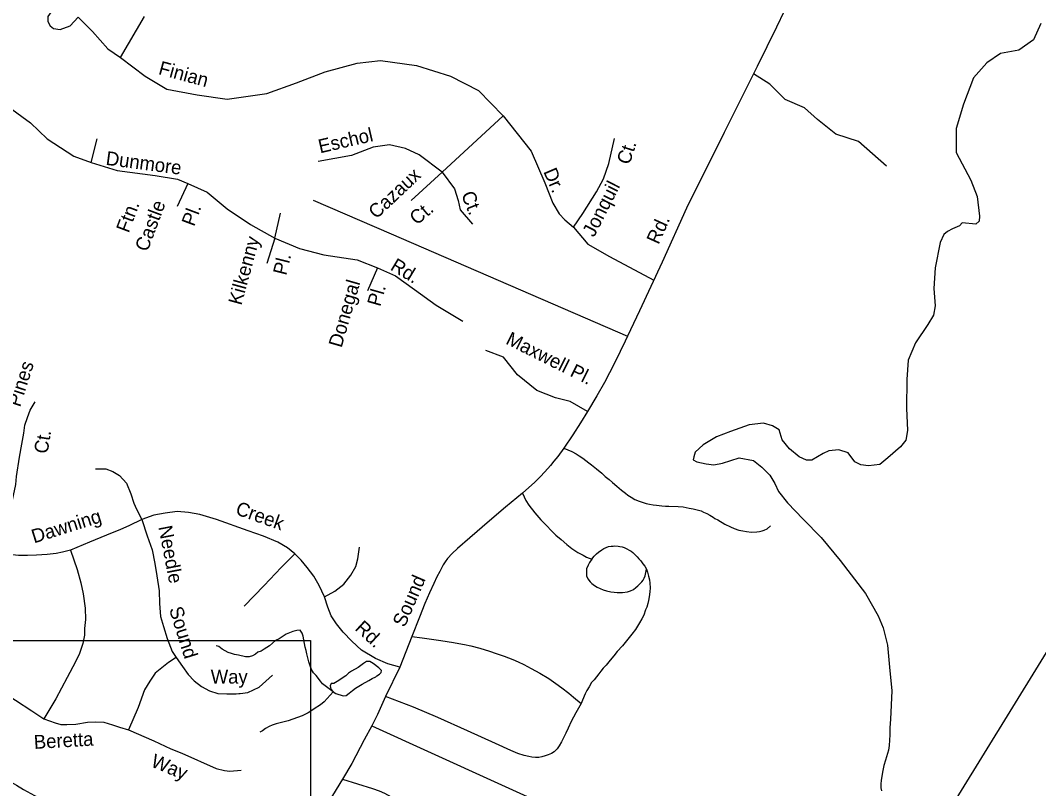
# Model space of a CAD drawing. Extents: x 1945482 to 2853149, y 66427 to 1015778.
# Drawn here: x 2344687 to 2349522, y 153897 to 157546 of the extents above; entities that cross this region are included whole.
import ezdxf

# ---------------------------------------------------------------- set-up
doc = ezdxf.new("R2010")
doc.units = 0
for name, color, linetype in [('Old_Level_10', 7, 'Continuous'), ('Old_Level_35', 7, 'Continuous'), ('Old_Level_48', 7, 'Continuous'), ('Old_Level_49', 7, 'Continuous'), ('Old_Level_59', 7, 'Continuous'), ('Old_Level_60', 7, 'Continuous'), ('Old_Level_63', 7, 'Continuous')]:
    doc.layers.add(name, color=color, linetype=linetype)

msp = doc.modelspace()

# ---------------------------------------------------------------- linework, layer by layer
at = {"layer": 'Old_Level_35'}
for p, q in [((2346077, 156693.2), (2346447.3, 156532.6)), ((2346447.3, 156532.6), (2347570.1, 156045.9))]:
    msp.add_line(p, q, dxfattribs=at)
for points in [[(2344345.4, 157787.9), (2344516.4, 157777.7), (2344670.4, 157757.1), (2344790.2, 157722.9), (2344892.8, 157651), (2344848.3, 157609.9), (2344817.5, 157565.4), (2344817.5, 157541.4), (2344827.8, 157520.9), (2344844.9, 157507.2), (2344875.7, 157503.8), (2344923.6, 157520.9), (2344961.3, 157562), (2345029.7, 157493.5), (2345101.5, 157411.3), (2345163.1, 157370.2), (2345276.1, 157565.4)], [(2348350.3, 157668.4), (2348276.4, 157513.5), (2348185.6, 157327.7), (2348028, 157013.6), (2347850.2, 156654.4), (2347734.3, 156397.8), (2347627.3, 156167.4), (2347570.1, 156045.9), (2347559.2, 156022.6), (2347510.9, 155924.5), (2347485, 155871.6), (2347460.9, 155826.7), (2347423.4, 155763.2), (2347380.3, 155689.3), (2347346.4, 155634.1), (2347310.5, 155578.5), (2347267.1, 155514.8), (2347238.5, 155475.6), (2347219.4, 155452.8), (2347204.4, 155432.2), (2347177.4, 155401.3), (2347154.4, 155378.4), (2347129.4, 155353.4), (2347071.4, 155300.9), (2346990.1, 155233.7), (2346914.5, 155168.7), (2346821.8, 155089.2), (2346761.8, 155038.6), (2346736.5, 155013.6), (2346715.5, 154990.8), (2346704.3, 154974.3), (2346694.7, 154960.1), (2346678.2, 154929.3), (2346665.1, 154902.8), (2346650.2, 154872), (2346630, 154827.2), (2346608.1, 154776.5), (2346582.7, 154711.5), (2346546.3, 154620.1), (2346488.1, 154473.7)], [(2345163.1, 157370.2), (2345279.5, 157281.2), (2345382.1, 157219.6), (2345525.8, 157192.2), (2345669.5, 157171.6), (2345857.7, 157199), (2345998, 157250.4), (2346134.9, 157301.7), (2346285.4, 157342.8), (2346397, 157356.5), (2346568.1, 157332.5), (2346728.9, 157281.2), (2346862.3, 157212.7), (2346978.7, 157092.9), (2347112.1, 156925.1), (2347177.1, 156774.4), (2347214.8, 156678.6), (2347245.6, 156627.2), (2347272.9, 156599.8), (2347312.6, 156564.9), (2347357.1, 156629.9), (2347422.1, 156732.7), (2347456.3, 156794.3), (2347480.3, 156866.2), (2347507.7, 156986)], [(2348246, 157242.9), (2348167.6, 157291.9)], [(2348798.9, 156853.2), (2348666.8, 156971.5), (2348559, 157006.3), (2348472.1, 157075.9), (2348409.5, 157131.5), (2348319.1, 157169.8), (2348246, 157242.9)], [(2344629.4, 157138.1), (2344735.4, 157059.3), (2344814.1, 156984), (2344940.7, 156901.8), (2345022.8, 156871), (2345146, 156833.3), (2345327.4, 156809.4), (2345433.4, 156792.2), (2345481.4, 156771.7), (2345573.7, 156730.6), (2345669.5, 156651.8), (2345779, 156576.5), (2345895.4, 156511.5), (2346011.7, 156463.5), (2346128.1, 156432.7), (2346285.4, 156408.7), (2346383.3, 156371.1), (2346468.8, 156333.4), (2346557.8, 156268.4), (2346660.5, 156193), (2346787.1, 156117.7)], [(2346978.7, 157092.9), (2346689.9, 156825.1), (2346542.8, 156691.6)], [(2345022.8, 156871), (2345052.3, 156984)], [(2346689.9, 156825.1), (2346580.4, 156907.3), (2346515.4, 156938.1), (2346440.1, 156955.2), (2346361.4, 156944.9), (2346258.8, 156903.9), (2346101.4, 156876.5)], [(2346689.9, 156825.1), (2346748.1, 156746.4), (2346765.2, 156691.6), (2346775.4, 156647.1), (2346833.6, 156578.6)], [(2345481.4, 156771.7), (2345432.1, 156662.1)], [(2345895.4, 156511.5), (2345921.4, 156631.3)], [(2347312.6, 156564.9), (2347381.1, 156482.7), (2347483.7, 156424.5)], [(2345895.4, 156511.5), (2345856.4, 156391.6)], [(2347483.7, 156424.5), (2347695, 156313.2)], [(2346383.3, 156371.1), (2346335.4, 156261.5)], [(2347380.3, 155689.3), (2347297.6, 155735.7), (2347227.2, 155753.4), (2347139.1, 155788.6), (2347046.7, 155863.5), (2346980.7, 155947.2), (2346897, 155978)], [(2344564.8, 155028.4), (2344575.6, 155055.3), (2344597.1, 155102), (2344618.6, 155148.6), (2344634.7, 155202.4), (2344645.5, 155247.2), (2344654.4, 155290.3), (2344665.2, 155342.3), (2344668.8, 155379.9), (2344683.1, 155471.4), (2344693.9, 155534.2), (2344702.8, 155586.2), (2344708.2, 155623.9), (2344720.7, 155659.7), (2344733.3, 155695.6), (2344756.6, 155735)], [(2347267.1, 155514.8), (2347305.8, 155498.3), (2347326.3, 155487.3), (2347340.5, 155477.6), (2347357, 155466.5), (2347385.7, 155445.6), (2347398.2, 155435.9), (2347423, 155416.9), (2347447.7, 155395.9), (2347464.4, 155380.5), (2347483.1, 155365.5), (2347497.7, 155351.9), (2347518.4, 155334.7), (2347541.2, 155315.6), (2347559.8, 155300.2), (2347572, 155290.9), (2347586.5, 155281.3), (2347605, 155270.2), (2347625.3, 155262.8), (2347639.3, 155257.4), (2347657.6, 155252.2), (2347673.8, 155248.9), (2347692, 155245.4), (2347708.1, 155244.1), (2347732.2, 155241.1), (2347750.3, 155239.8), (2347766.1, 155238.5), (2347810.1, 155238.2), (2347834.5, 155235.3), (2347862.6, 155230.1), (2347880.8, 155226.9), (2347894.7, 155223.5), (2347919.3, 155216.6), (2347931.3, 155210.9), (2347945.7, 155203.6), (2347960.1, 155196.3), (2347976.2, 155186.7), (2347984.7, 155181.1), (2347998.8, 155173.5), (2348031.7, 155152.8), (2348058.2, 155140.1), (2348076.5, 155132.6), (2348098.8, 155125.6), (2348117, 155122.4), (2348135.1, 155119.2), (2348159.2, 155115.9), (2348183.2, 155116.8), (2348197.2, 155119.3), (2348208.9, 155122.1), (2348219, 155124.4), (2348232.5, 155130.9), (2348248, 155145.6)], [(2345043.3, 155415.8), (2345093.5, 155415.8), (2345125.7, 155403.3), (2345158, 155385.3), (2345190.2, 155347.7), (2345211.8, 155297.4), (2345226.1, 155252.6), (2345238.7, 155224.8), (2345263.7, 155175.5)], [(2347071.4, 155300.9), (2347086.9, 155265.8), (2347101.6, 155244), (2347129.3, 155207.4), (2347158.5, 155174.4), (2347183.4, 155149.5), (2347210.5, 155120.3), (2347229.3, 155101.1), (2347254.1, 155080), (2347281.3, 155057.2), (2347306, 155038.1), (2347334.6, 155019.2), (2347359.1, 155006.4), (2347375.6, 154996.9), (2347399.9, 154988)], [(2345989.5, 155012.3), (2345955.4, 155041), (2345908.8, 155067.9), (2345840.8, 155096.6), (2345769.1, 155121.7), (2345618.5, 155175.5), (2345539.7, 155198.8), (2345485.9, 155209.6), (2345432.2, 155213.2), (2345374.8, 155206), (2345321.1, 155197), (2345263.7, 155175.5)], [(2345263.7, 155175.5), (2345201.6, 155145.2), (2345161.6, 155128.9), (2345095.3, 155102), (2345014.6, 155067.9), (2344925, 155030.2)], [(2345263.7, 155175.5), (2345289.7, 155097.5), (2345313, 155031.1), (2345325.5, 154966.6), (2345334.5, 154907.4), (2345345.3, 154837.4), (2345347, 154776.4), (2345352.4, 154715.5), (2345366.8, 154667), (2345384.7, 154609.7), (2345408, 154548.7), (2345426.8, 154520.9)], [(2344925, 155030.2), (2344887.4, 155021.3), (2344856.9, 155014.1), (2344813.9, 155008.7), (2344763.7, 155006.9), (2344720.7, 155005.1), (2344677.7, 155005.1), (2344634.7, 155008.7), (2344602.5, 155014.1), (2344564.8, 155028.4)], [(2344925, 155030.2), (2344956.4, 154937.9), (2344974.3, 154875.1), (2344985.1, 154823.1), (2344994, 154754.9), (2344995.8, 154701.1), (2344992.2, 154658.1), (2344992.2, 154625.8), (2344983.3, 154586.3), (2344967.1, 154539.7), (2344949.2, 154500.3), (2344909.8, 154424.9), (2344856, 154324.5), (2344798.7, 154229.4)], [(2345989.5, 155012.3), (2345925, 154947.7), (2345844.3, 154861.6), (2345749.4, 154764.8)], [(2346131.1, 154807.8), (2346106, 154861.6), (2346080.9, 154906.5), (2346048.6, 154947.7), (2346020, 154981.8), (2345989.5, 155012.3)], [(2346131.1, 154807.8), (2346179.4, 154834.7), (2346222.5, 154868.8), (2346256.5, 154911.9), (2346279.8, 154953.1), (2346288.8, 154989), (2346297.7, 155044.6)], [(2347399.9, 154988), (2347411.5, 155002.2), (2347422.9, 155012.9), (2347432.7, 155021.1), (2347448.4, 155031.9), (2347458, 155038.2), (2347468, 155042.6), (2347479.6, 155047), (2347491.7, 155049.4), (2347501.5, 155049.8), (2347509.7, 155050.1), (2347525.5, 155048.8), (2347533.8, 155047.1), (2347543.7, 155045.5), (2347554, 155042), (2347566, 155036.6), (2347578.4, 155030.8), (2347586.5, 155025.3), (2347594.9, 155019.7), (2347603.1, 155011.8), (2347615.8, 154998.5), (2347624, 154988.7), (2347632.3, 154979.1), (2347643, 154965.5), (2347651.3, 154954), (2347660.1, 154940.2)], [(2347399.9, 154988), (2347388.7, 154971.5), (2347383, 154959.1), (2347375.8, 154940.8), (2347374.4, 154926.9), (2347375.1, 154908.9), (2347381.6, 154893.1), (2347392.4, 154879.4), (2347400.5, 154871.8), (2347413.1, 154862.5), (2347425.2, 154854.8), (2347439.6, 154847.5), (2347453.9, 154842.1), (2347469.9, 154836.5), (2347490.1, 154831.4), (2347506.2, 154830.1), (2347520.4, 154828.7), (2347532.2, 154829.1), (2347546.3, 154829.7), (2347570.1, 154832.6), (2347584.1, 154837.1), (2347597.6, 154843.5), (2347609.4, 154852.2), (2347619.3, 154860.5), (2347630.6, 154871.1), (2347638.2, 154879.3), (2347644.1, 154887.4), (2347649.6, 154897.8), (2347653.2, 154907.8), (2347660.1, 154940.2)], [(2347660.1, 154940.2), (2347664.6, 154926.3), (2347669.3, 154906.4), (2347673.9, 154888.6), (2347676.5, 154872.9), (2347677.4, 154851), (2347676.1, 154832.9), (2347673.2, 154808.5), (2347669.9, 154790.6), (2347666.6, 154776.4), (2347661, 154760), (2347655.6, 154746.1), (2347646.7, 154721.4), (2347637.3, 154703.3), (2347626.2, 154684.8), (2347616.7, 154668.4), (2347607.4, 154653.9), (2347590.2, 154631.2), (2347571.2, 154606.5), (2347546.5, 154575.7), (2347521.3, 154548.4), (2347504.1, 154527.7), (2347487.2, 154507), (2347468.1, 154484.3), (2347454.5, 154469.9), (2347442.9, 154455.4), (2347433.6, 154442.9), (2347410.8, 154414.1), (2347399.1, 154401.5), (2347388.1, 154381.3), (2347376.7, 154362.8), (2347369.4, 154348.4), (2347356.5, 154318), (2347349.2, 154301.7)], [(2346488.1, 154473.7), (2346432.1, 154490.4), (2346373, 154515.5), (2346306.7, 154555), (2346260.1, 154598), (2346218.9, 154641), (2346188.4, 154680.5), (2346163.3, 154718.2), (2346147.2, 154759.4), (2346131.1, 154807.8)], [(2346546.3, 154620.1), (2346594.5, 154613.8), (2346638.7, 154607.7), (2346660.8, 154604.6), (2346682.9, 154601.2), (2346713.3, 154596.5), (2346743.4, 154591.8), (2346769.5, 154586.9), (2346796, 154581.7), (2346826.1, 154575.1), (2346868.5, 154564.6), (2346915, 154550.7), (2346945.6, 154539.7), (2346983.9, 154527.1), (2347024.6, 154510.7), (2347051.3, 154499.9), (2347077.7, 154486.9), (2347112.3, 154468.2), (2347153.2, 154445.9), (2347196.2, 154419.7), (2347229.3, 154397), (2347258, 154376.2), (2347291.2, 154351.2), (2347313.9, 154332.1), (2347349.2, 154301.7)], [(2345426.8, 154520.9), (2345391, 154495.8), (2345358.7, 154470.7), (2345326.4, 154445.6), (2345301.4, 154407.9), (2345276.3, 154366.6), (2345245.8, 154282.4), (2345201, 154176.5)], [(2345426.8, 154520.9), (2345457.3, 154477.8), (2345484.1, 154440.2), (2345512.8, 154409.7), (2345546.9, 154382.8), (2345584.5, 154361.3), (2345623.9, 154348.7), (2345666.9, 154346.9), (2345711.7, 154346.9), (2345724.4, 154348.5), (2345730.1, 154349.3)], [(2345730.1, 154349.3), (2345767.3, 154354.1), (2345821, 154379.2), (2345883.8, 154436.6)], [(2346488.1, 154473.7), (2346421.4, 154334.9), (2346382.8, 154249.3), (2346355, 154196.4), (2346319.6, 154128.7), (2346260, 154016.4), (2346217, 153942.8), (2346134.1, 153807.2), (2346044.2, 153655.7), (2345936.8, 153483.4), (2345813.2, 153273.7)], [(2344492.3, 154424.9), (2344578.3, 154371.1), (2344664.3, 154317.3), (2344741.3, 154267.1), (2344798.7, 154229.4)], [(2347349.2, 154301.7), (2347324.8, 154256.7), (2347302.4, 154215.8), (2347287.6, 154185), (2347276.7, 154160.6), (2347265.5, 154138.2), (2347256.3, 154119.8), (2347244.9, 154101.3), (2347235.6, 154087.1), (2347222.1, 154072.5), (2347208.3, 154064.1), (2347192.8, 154057.2), (2347178.9, 154052.7), (2347163, 154048.1), (2347149, 154045.6), (2347133.3, 154045), (2347115.2, 154046.3), (2347100.9, 154049.6), (2347078.7, 154054.7), (2347048.5, 154063.6), (2347015.8, 154078.4), (2346942.6, 154111.3), (2346809.9, 154172.4), (2346669.5, 154234.7), (2346553.4, 154284), (2346421.4, 154334.9)], [(2344798.7, 154229.4), (2344851.6, 154210.6), (2344878.4, 154201.6), (2344907.1, 154201.6), (2344950.1, 154203.4), (2345005.7, 154212.4), (2345045.1, 154214.2), (2345082.7, 154212.4), (2345123.9, 154199.9), (2345158, 154189.1), (2345201, 154176.5)], [(2346355, 154196.4), (2347535.3, 153659.3)], [(2345201, 154176.5), (2345321.1, 154124.5), (2345401.7, 154086.9), (2345453.7, 154065.3), (2345616.7, 153993.6), (2345656.2, 153982.8), (2345681.3, 153981.1), (2345735, 153984.6)], [(2343938.9, 154016.8), (2344260.2, 153991.4), (2344452.9, 153975.1), (2344499, 153970.7), (2344529.3, 153967.9), (2344549.5, 153964.8), (2344559.4, 153963.2), (2344571.7, 153959.8), (2344583.6, 153956), (2344606, 153947), (2344634.8, 153932.1), (2344669.3, 153913.4), (2344702.3, 153892.7), (2344753.3, 153864.9), (2344929.2, 153765.8), (2345152.2, 153646.6), (2345479.6, 153459.4), (2345813.2, 153273.7)], [(2346217, 153942.8), (2346358.6, 153898.2), (2346391.2, 153887.6), (2346415.6, 153876.5), (2346448.1, 153857.7), (2346464.7, 153846.6), (2346485.3, 153831.3), (2346504, 153814), (2346522.8, 153796.7), (2346541.4, 153781.3), (2346555.7, 153770.1), (2346582.6, 153753.1), (2346598.7, 153743.6), (2346619.1, 153734.5), (2346645.9, 153721.5), (2346682.1, 153709.1), (2346706.7, 153701.9), (2346742.8, 153693.5)]]:
    msp.add_lwpolyline(points, dxfattribs=at)
at = {"layer": 'Old_Level_48'}
msp.add_lwpolyline([(2349898.6, 155096.5), (2347115.6, 150577.3), (2346798.3, 150771.2), (2346691.4, 150757.8), (2346571.1, 150677.6), (2346303.8, 150741.1), (2346043.2, 150687.6), (2345846.1, 150737.8), (2345622.3, 150764.5), (2345445.2, 151015.2), (2345298.2, 151031.9), (2345137.9, 151219.1), (2345174.6, 151449.7), (2345007.6, 151265.9), (2344880.6, 151272.6), (2344747, 151456.4), (2344556.6, 151456.4)], dxfattribs=at)
at = {"layer": 'Old_Level_49'}
msp.add_lwpolyline([(2349898.6, 155096.5), (2347115.6, 150577.3), (2346798.3, 150771.2), (2346691.4, 150757.8), (2346571.1, 150677.6), (2346303.8, 150741.1), (2346043.2, 150687.6), (2345846.1, 150737.8), (2345622.3, 150764.5), (2345445.2, 151015.2), (2345298.2, 151031.9), (2345137.9, 151219.1), (2345174.6, 151449.7), (2345007.6, 151265.9), (2344880.6, 151272.6), (2344747, 151456.4), (2344556.6, 151456.4)], dxfattribs=at)
at = {"layer": 'Old_Level_59'}
for points in [[(2346172.7, 154357.8), (2346122, 154395.5), (2346112, 154407.3), (2346091.7, 154434.9), (2346079.2, 154446.8), (2346070, 154462.9), (2346062.2, 154480.4), (2346056, 154499.2), (2346046.5, 154538.3), (2346043.7, 154554.1), (2346039.5, 154569.9), (2346029.2, 154621.5), (2346025, 154636), (2346015.5, 154649.4), (2345999.2, 154648.7), (2345981, 154644.3), (2345949.5, 154631.6), (2345915.7, 154608.7), (2345899, 154600.3), (2345869.2, 154576.1), (2345844, 154559.3), (2345830, 154551), (2345814.7, 154545.5), (2345803, 154536.2), (2345788.5, 154527.7), (2345773, 154522.6), (2345755.7, 154523.1), (2345723.2, 154531.8), (2345704.2, 154535.1), (2345689.2, 154539.1), (2345674, 154544.3), (2345659, 154551.8), (2345644.5, 154560.4), (2345629.5, 154572.3), (2345616.5, 154575)], [(2346172.7, 154357.8), (2346129.7, 154309.7), (2346112.5, 154295.5), (2346081.2, 154276.3), (2346066.7, 154266), (2346053.5, 154257.7), (2346025.7, 154243.6), (2345957.7, 154219.5), (2345901.5, 154205.7), (2345882.2, 154198.9), (2345868.5, 154192.7), (2345850.5, 154183.2), (2345837, 154172), (2345824.7, 154164.8)]]:
    msp.add_lwpolyline(points, dxfattribs=at)
at = {"layer": 'Old_Level_60'}
for points in [[(2349533, 157531), (2349498, 157454.4), (2349428, 157405.2), (2349340.2, 157388.7), (2349276.2, 157345), (2349212, 157273.8), (2349165.2, 157147.9), (2349130.2, 157033), (2349130.2, 156918.1), (2349200.2, 156786.7), (2349229.5, 156710.1), (2349241.2, 156617.1), (2349238.7, 156592.7), (2349223.5, 156578.8), (2349159.5, 156584.2), (2349145.7, 156570.4), (2349112.7, 156556.9), (2349089.5, 156544), (2349072.2, 156529.8), (2349054.2, 156491.2), (2349031, 156370.8), (2349024.5, 156272.3), (2349031, 156190.2), (2349022.5, 156146.6), (2348996, 156102.6), (2348937.7, 156015.1), (2348902.5, 155933), (2348896.7, 155839.9), (2348894.7, 155704.6), (2348899.7, 155599.1), (2348891.5, 155552.5), (2348865.7, 155520.1), (2348806.2, 155467.8), (2348768.2, 155436.9), (2348714.2, 155430.9), (2348678, 155434.9), (2348649.5, 155449.1), (2348617, 155491.7), (2348572.7, 155506.1), (2348526.2, 155501.8), (2348498, 155489.7), (2348444.5, 155456.8), (2348420.2, 155457.2), (2348385.5, 155473.4), (2348339.5, 155511.6), (2348303.5, 155554.6), (2348290.5, 155601.2), (2348257.7, 155621), (2348214.7, 155633.6), (2348147.7, 155625.5), (2348059.2, 155593.7), (2347992, 155568.7), (2347929.2, 155530.2), (2347890.5, 155495.7), (2347884.2, 155473.2), (2347881.7, 155459.3), (2347899, 155449.1), (2347942.5, 155440.4), (2347979, 155434.9), (2348020.2, 155443), (2348100, 155467.8), (2348167.2, 155455.2), (2348208.2, 155424.8), (2348245, 155386.3), (2348269.2, 155347.4), (2348286.2, 155309.2), (2348329.5, 155254.5), (2348403.5, 155177.7), (2348489.5, 155090.2), (2348578.7, 154980.7), (2348699.2, 154824.6), (2348759.5, 154718), (2348783.5, 154660.4), (2348805, 154579.3), (2348813.7, 154473.8), (2348824.5, 154362.3), (2348819.2, 154227.5), (2348816, 154185.5), (2348815.5, 154153.2), (2348812, 154102.6), (2348809, 154079.9), (2348795.5, 154032.2), (2348787, 154007.7), (2348781.5, 153984), (2348773.5, 153937.9), (2348772.5, 153918.6), (2348773, 153900.4)], [(2346185, 154349.5), (2346218.9, 154338.9), (2346234.2, 154339.9), (2346248.2, 154350.7), (2346263.2, 154363.7), (2346278.2, 154374.9), (2346309.4, 154393.2), (2346341.7, 154410.7), (2346357.7, 154420.7), (2346374.4, 154428), (2346379.9, 154433.5), (2346391.4, 154441.8), (2346400.2, 154449.1), (2346401.7, 154458.9), (2346389.2, 154471.7), (2346362.2, 154492.5), (2346346.9, 154501.4), (2346331.2, 154501.4), (2346315.7, 154491.3), (2346290.2, 154473.1), (2346259.7, 154454.9), (2346245.2, 154445.4), (2346231.7, 154432.9), (2346190.9, 154405.8), (2346175.2, 154396.9), (2346162.4, 154396.5), (2346161.1, 154393.3)], [(2346161.1, 154393.3), (2346157.9, 154385.5), (2346160.7, 154370.5), (2346172.7, 154357.8), (2346185, 154349.5)], [(2348773, 153900.4), (2348776.5, 153887)]]:
    msp.add_lwpolyline(points, dxfattribs=at)
at = {"layer": 'Old_Level_63'}
msp.add_lwpolyline([(2346064.1, 148689.8), (2332656.4, 148689.8), (2332656.4, 154600.9), (2346064.1, 154600.9)], close=True, dxfattribs=at)

# ---------------------------------------------------------------- texts
at = {"layer": 'Old_Level_10'}
for s, height, rotation, p in [('Finian', 65.62, 344.7816, (2345338.7, 157291.5)), ('Eschol', 65.62, 12.944, (2346109.9, 156914.7)), ('Ct.', 65.62, 71.8359, (2347578.8, 156857.2)), ('Dunmore', 65.62, 352.4054, (2345089.9, 156860.7)), ('Dr.', 65.62, 293.2197, (2347169.1, 156828.4)), ('Cazaux', 65.62, 43.2871, (2346377.1, 156600)), ('Jonquil', 65.62, 63.1422, (2347410.9, 156513.3)), ('Ct.', 65.62, 291.9325, (2346778.7, 156719.7)), ('Ftn.', 65.62, 69.4444, (2345201, 156533.4)), ('Castle', 65.62, 69.4444, (2345290.1, 156443.9)), ('Pl.', 65.62, 69.4444, (2345511.7, 156564.2)), ('Ct.', 65.62, 39.6877, (2346568.9, 156571.1)), ('Rd.', 65.62, 65.7005, (2347716.9, 156478.6)), ('Kilkenny', 65.62, 74.7448, (2345736.3, 156189.9)), ('Pl.', 65.62, 75.9638, (2345948.9, 156332.1)), ('Rd.', 65.62, 329.0362, (2346439, 156364.3)), ('Donegal', 65.62, 74.0545, (2346212, 155988.4)), ('Pl.', 65.62, 74.0545, (2346395.2, 156183.8)), ('Maxwell Pl.', 65.617, 333.4367, (2346987.1, 156011.9)), ('Pines', 65.62, 72.2974, (2344685.5, 155706.5)), ('Ct.', 65.62, 80.6315, (2344815.5, 155485)), ('Creek', 65.62, 340.3319, (2345704, 155202)), ('Dawning', 65.62, 17.4577, (2344751.8, 155061.8)), ('Needle', 65.62, 280.9944, (2345341.9, 155140.5)), ('Sound', 65.62, 66.5988, (2346512.1, 154660.3)), ('Sound', 65.62, 287.3409, (2345392.2, 154750.8)), ('Rd.', 65.62, 317.2679, (2346271.7, 154654.2)), ('Beretta', 65.62, 3.2485, (2344752.7, 154085.7)), ('Way', 65.62, 337.5046, (2345301.7, 154004))]:
    msp.add_text(s, height=height, rotation=rotation, dxfattribs=at).set_placement(p)
msp.add_text('Way', height=65.62, dxfattribs=at).set_placement((2345590.8, 154396.1))

doc.saveas('drawing.dxf')
